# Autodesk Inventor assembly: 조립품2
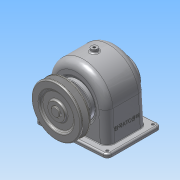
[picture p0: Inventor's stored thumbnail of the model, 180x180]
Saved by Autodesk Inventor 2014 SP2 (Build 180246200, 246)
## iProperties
Created: 2016-01
Part Number: 조립품2
Document SubType Name: Assembly
Designer: User
Author: User
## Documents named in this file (16)
- C:\Documents and Settings\User\My Documents\Inventor\460106V1014\조립품2.iam
- C:\Documents and Settings\User\My Documents\Inventor\460106V1014\본체.ipt
- C:\Documents and Settings\User\My Documents\Inventor\460106V1014\축.ipt
- C:\Documents and Settings\User\My Documents\Inventor\460106V1014\뒤커버.ipt
- C:\Documents and Settings\User\My Documents\Inventor\460106V1014\베어링 6203.ipt
- C:\Documents and Settings\User\My Documents\Inventor\460106V1014\오일씰 28 40 8.ipt
- C:\Documents and Settings\User\My Documents\Inventor\460106V1014\부시1.ipt
- C:\Documents and Settings\User\My Documents\Inventor\460106V1014\부시2.ipt
- C:\Documents and Settings\User\My Documents\Inventor\460106V1014\스퍼기어.ipt
- C:\Documents and Settings\User\My Documents\Inventor\460106V1014\키 - 6 x 6 x 22.ipt
- C:\Documents and Settings\User\My Documents\Inventor\460106V1014\키 - 5 x 5 x 18.ipt
- C:\Documents and Settings\User\My Documents\Inventor\460106V1014\앞커버.ipt
- C:\Documents and Settings\User\My Documents\Inventor\460106V1014\V-벨트풀리.ipt
- C:\Documents and Settings\User\My Documents\Inventor\460106V1014\멈춤나사 - M4x10.ipt
- C:\Documents and Settings\User\My Documents\Inventor\460106V1014\볼트 M3 x 10.ipt
- C:\Documents and Settings\User\My Documents\Inventor\460106V1014\볼트 M3 x 8.ipt
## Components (9 placed, 3 different names)
1. V-벨트풀리:1
2. ISO 4762 M3 x 8:1
3. ISO 4762 M3 x 10:1
4. ISO 4762 M3 x 8:2
5. ISO 4762 M3 x 10:2
6. ISO 4762 M3 x 8:3
7. ISO 4762 M3 x 10:3
8. ISO 4762 M3 x 8:4
9. ISO 4762 M3 x 10:4
